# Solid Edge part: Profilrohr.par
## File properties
Username: bmolnar
Dokumentum tartalom típus: 0
Author: bmolnar
Last saved by: bmolnar
Revision: 83
Sűrűség: 0,000 kg/m^3
Pontosság: 0,990
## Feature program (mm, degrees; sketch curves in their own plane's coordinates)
base feature "unnamed BaseFeature 1"
thread "unnamed Thread 1"
thread "Menet_2"  ThreadDepth = 9.3 mm
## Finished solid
Body 1: solid body, 177 faces, 454 edges, 298 vertices.
  Faces by surface: plane 102, cylinder 65, cone 6, torus 4
  Edges by curve: line 308, circle 136, curve on surface 7, spline 2, intersection 1
Bounding box of the edges (mm; curved faces can reach further): 124.000 x 131.000 x 116.000, from (-62, -62, 0) to (62, 69, 116).
Cylindrical faces by radius (mm): R0.2 x24, R2.625 x2, R5.5 x8, R5.7225 x4, R8.6 x16, R50 x1, R50.85 x2, R51.1 x2, R53.1 x2, R84 x4
Conical faces (half-angle, radius in mm at the cone's reference point): 30 deg R50.325 x2, 30 deg R51.283 x2, 45 deg R6.0725 x2
Toroidal faces (ring radius, tube radius in mm): R52.9 r0.2 x4
Planar faces by outward normal: +x 9, +y 11, +z 8, -x 9, -y 9, -z 8, oblique 48
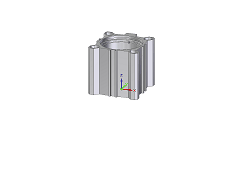
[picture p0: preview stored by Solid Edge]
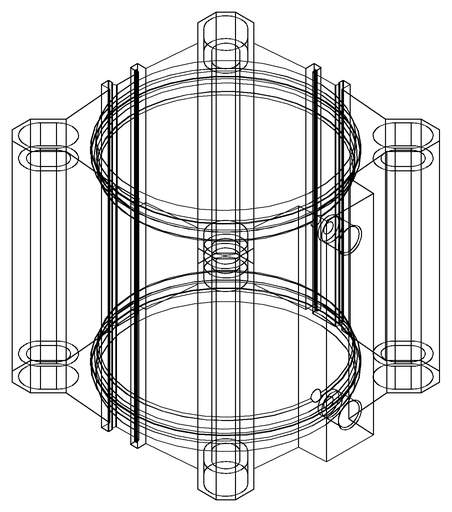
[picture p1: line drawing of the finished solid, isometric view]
